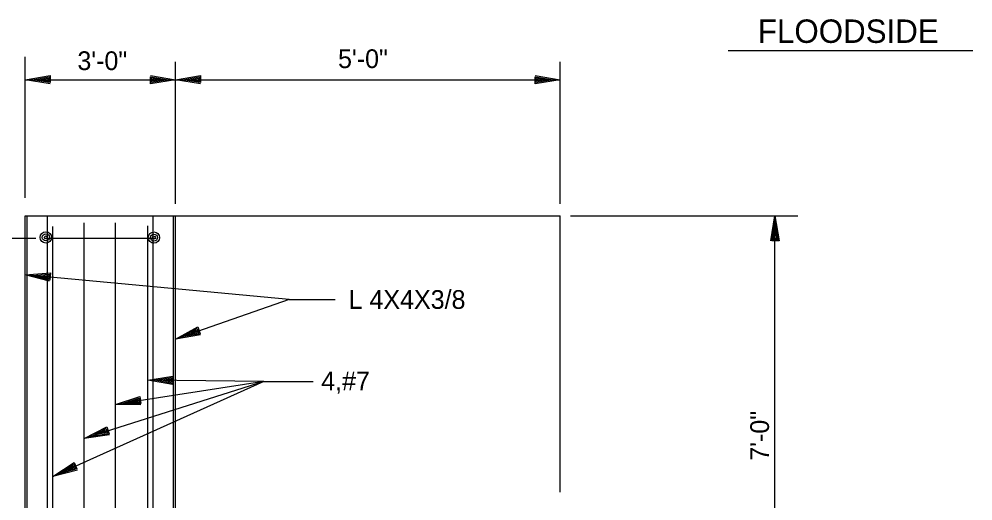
# Model space of a CAD drawing. Extents: x 6 to 106, y 3 to 74.
# Drawn here: x 84.18 to 103.19, y 63.29 to 72.89 of the extents above; entities that cross this region are included whole.
import ezdxf

# ---------------------------------------------------------------- set-up
doc = ezdxf.new("R2010")
doc.units = 0
for name, color, linetype in [('Level 22', 7, 'Continuous'), ('Level 44', 7, 'Continuous'), ('Level 50', 7, 'Continuous')]:
    doc.layers.add(name, color=color, linetype=linetype)

msp = doc.modelspace()

# ---------------------------------------------------------------- linework, layer by layer
at = {"layer": 'Level 22'}
for p, q in [((84.295, 69.332), (84.295, 72.14)), ((98.311, 72.269), (103.194, 72.269)), ((87.295, 69.21), (87.295, 72.043)), ((94.962, 69.215), (94.962, 72.043)), ((84.295, 71.686), (87.295, 71.686)), ((87.295, 71.686), (94.962, 71.686)), ((84.295, 55.863), (84.295, 68.974)), ((84.295, 68.974), (94.962, 68.974)), ((84.337, 59.641), (84.337, 68.974)), ((84.74, 59.641), (84.74, 68.974)), ((86.851, 59.641), (86.851, 68.974)), ((87.253, 59.641), (87.253, 68.974)), ((87.295, 59.641), (87.295, 68.974)), ((94.962, 63.469), (94.962, 68.974)), ((95.168, 68.974), (99.7, 68.974)), ((99.246, 59.641), (99.246, 68.974)), ((84.851, 56.948), (84.851, 68.763)), ((85.476, 56.994), (85.476, 68.835)), ((86.101, 56.948), (86.101, 68.835)), ((86.74, 56.923), (86.74, 68.777)), ((80.362, 68.53), (84.509, 68.53)), ((84.711, 68.53), (86.909, 68.53)), ((89.562, 67.31), (84.295, 67.798)), ((89.562, 67.31), (87.295, 66.517)), ((89.562, 67.31), (90.477, 67.31))]:
    msp.add_line(p, q, dxfattribs=at)
at = {"layer": 'Level 44'}
for q in [(84.851, 63.779), (85.476, 64.538), (86.101, 65.215), (86.74, 65.7), (90.038, 65.676)]:
    msp.add_line((89.055, 65.676), q, dxfattribs=at)
at = {"layer": 'Level 50'}
for p, q in [((84.295, 71.686), (84.295, 71.686)), ((84.434, 71.686), (84.434, 71.686)), ((87.156, 71.686), (87.156, 71.686)), ((87.295, 71.686), (87.295, 71.686)), ((87.295, 71.686), (87.295, 71.686)), ((87.434, 71.686), (87.434, 71.686)), ((94.823, 71.686), (94.823, 71.686)), ((94.962, 71.686), (94.962, 71.686)), ((99.246, 68.974), (99.246, 68.974)), ((99.246, 68.974), (99.246, 68.974)), ((99.246, 68.97), (99.246, 68.97)), ((99.246, 68.835), (99.246, 68.835)), ((84.295, 67.798), (84.295, 67.798)), ((84.433, 67.785), (84.433, 67.785)), ((87.295, 66.517), (87.295, 66.517)), ((87.426, 66.562), (87.426, 66.562)), ((86.74, 65.7), (86.74, 65.7)), ((86.878, 65.698), (86.878, 65.698)), ((86.238, 65.237), (86.238, 65.237)), ((86.101, 65.215), (86.101, 65.215)), ((85.476, 64.538), (85.476, 64.538)), ((85.608, 64.58), (85.608, 64.58)), ((84.851, 63.779), (84.851, 63.779)), ((84.977, 63.836), (84.977, 63.836))]:
    msp.add_line(p, q, dxfattribs=at)
for points in [[(84.794, 71.604), (84.295, 71.686), (84.794, 71.769), (84.794, 71.628), (84.434, 71.686), (84.772, 71.742), (84.772, 71.652), (84.567, 71.686), (84.751, 71.716), (84.751, 71.678), (84.706, 71.686)], [(86.796, 71.769), (87.295, 71.686), (86.796, 71.604), (86.796, 71.745), (87.156, 71.686), (86.818, 71.63), (86.818, 71.721), (87.023, 71.686), (86.839, 71.657), (86.839, 71.694), (86.884, 71.686)], [(87.794, 71.604), (87.295, 71.686), (87.794, 71.769), (87.794, 71.628), (87.434, 71.686), (87.772, 71.742), (87.772, 71.652), (87.567, 71.686), (87.751, 71.716), (87.751, 71.678), (87.706, 71.686)], [(94.463, 71.769), (94.962, 71.686), (94.463, 71.604), (94.463, 71.745), (94.823, 71.686), (94.484, 71.63), (94.484, 71.721), (94.69, 71.686), (94.506, 71.657), (94.506, 71.694), (94.551, 71.686)], [(99.163, 68.475), (99.246, 68.974), (99.328, 68.475), (99.187, 68.475), (99.246, 68.835), (99.302, 68.497), (99.211, 68.497), (99.246, 68.702), (99.275, 68.518), (99.238, 68.518), (99.246, 68.563)], [(99.243, 68.958), (99.246, 68.974), (99.248, 68.958), (99.244, 68.958), (99.246, 68.97), (99.248, 68.959), (99.245, 68.959), (99.246, 68.966), (99.247, 68.96), (99.246, 68.96), (99.246, 68.961)], [(84.784, 67.67), (84.295, 67.798), (84.799, 67.835), (84.786, 67.694), (84.433, 67.785), (84.776, 67.81), (84.767, 67.72), (84.566, 67.773), (84.752, 67.785), (84.748, 67.748), (84.704, 67.76)], [(87.793, 66.603), (87.295, 66.517), (87.738, 66.759), (87.785, 66.626), (87.426, 66.562), (87.727, 66.727), (87.757, 66.642), (87.552, 66.606), (87.716, 66.695), (87.728, 66.66), (87.683, 66.652)], [(87.237, 65.612), (86.74, 65.7), (87.239, 65.777), (87.238, 65.636), (86.878, 65.698), (87.217, 65.751), (87.217, 65.66), (87.012, 65.697), (87.196, 65.724), (87.195, 65.687), (87.15, 65.695)], [(86.606, 65.21), (86.101, 65.215), (86.581, 65.374), (86.602, 65.234), (86.238, 65.237), (86.564, 65.344), (86.578, 65.254), (86.369, 65.257), (86.547, 65.314), (86.552, 65.278), (86.506, 65.278)], [(85.976, 64.61), (85.476, 64.538), (85.926, 64.768), (85.969, 64.633), (85.608, 64.58), (85.914, 64.736), (85.941, 64.65), (85.735, 64.621), (85.901, 64.704), (85.913, 64.669), (85.867, 64.663)], [(85.339, 63.908), (84.851, 63.779), (85.271, 64.059), (85.329, 63.93), (84.977, 63.836), (85.263, 64.026), (85.3, 63.943), (85.099, 63.891), (85.254, 63.993), (85.27, 63.959), (85.225, 63.948)]]:
    msp.add_lwpolyline(points, dxfattribs=at)
for centre, radius in [((84.709, 68.545), 0.113), ((84.709, 68.545), 0.0703), ((84.709, 68.545), 0.0281), ((86.864, 68.54), 0.113), ((86.864, 68.54), 0.0703), ((86.864, 68.54), 0.0281)]:
    msp.add_circle(centre, radius, dxfattribs=at)

# ---------------------------------------------------------------- texts
at = {"layer": 'Level 22'}
for s, height, p in [('FLOODSIDE', 0.4667, (98.906, 72.419)), ('5\'-0"', 0.3733, (90.535, 71.917)), ('3\'-0"', 0.3733, (85.338, 71.877)), ('L 4X4X3/8', 0.3733, (90.745, 67.12)), ('4,#7', 0.3733, (90.199, 65.497))]:
    msp.add_text(s, height=height, dxfattribs=at).set_placement(p)
msp.add_text('7\'-0"', height=0.3733, rotation=90, dxfattribs=at).set_placement((99.128, 64.094))

doc.saveas('drawing.dxf')
